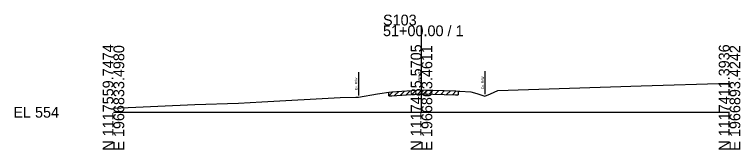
# Model space of a CAD drawing. Extents: x -26 to 163, y -10 to 24018.
# Drawn here: x -25.7 to 162.8, y 490.3 to 525.5 of the extents above; entities that cross this region are included whole.
import ezdxf

# ---------------------------------------------------------------- set-up
doc = ezdxf.new("R2010")
doc.units = 0
for name, color, linetype in [('RD_GPK_XS_Cell', 7, 'Continuous'), ('RD_XS_ExGround', 7, 'Continuous'), ('RD_XS_ExPaveRet', 7, 'Continuous'), ('RD_XS_ExRW', 7, 'Continuous'), ('RD_XS_TX_Elev_EX', 7, 'Continuous')]:
    doc.layers.add(name, color=color, linetype=linetype)

msp = doc.modelspace()

# ---------------------------------------------------------------- linework, layer by layer
at = {"layer": 'RD_GPK_XS_Cell'}
for p, q in [((80, 500), (80, 522.62)), ((0, 500), (80, 500)), ((80, 500), (160, 500))]:
    msp.add_line(p, q, dxfattribs=at)
at = {"layer": 'RD_XS_ExGround'}
msp.add_lwpolyline([(0, 501.08), (21.15, 501.99), (32.51, 502.36), (38.55, 502.7), (58.89, 503.85), (62.97, 503.9), (63.61, 503.91), (68.61, 504.78), (69.19, 504.87), (71.52, 505.26), (72.32, 505.31), (80.02, 505.81), (88.8, 505.56), (89.51, 505.54), (89.92, 505.51), (92.85, 505.32), (94.34, 504.91), (96.47, 504.2), (97.92, 504.77), (99.86, 505.71), (137.06, 506.89), (160, 507.54)], dxfattribs=at)
at = {"layer": 'RD_XS_ExPaveRet'}
for p, q in [((71.52, 504.26), (72.59, 505.33)), ((73.02, 504.36), (74.09, 505.43)), ((74.52, 504.45), (75.59, 505.52)), ((76.02, 504.55), (77.09, 505.62)), ((77.52, 504.65), (78.59, 505.72)), ((79.02, 504.75), (80.09, 505.81)), ((80.52, 504.8), (81.49, 505.77)), ((82.02, 504.75), (82.99, 505.73)), ((83.52, 504.71), (84.49, 505.68)), ((85.02, 504.67), (85.99, 505.64)), ((86.52, 504.62), (87.49, 505.6)), ((88.02, 504.58), (88.99, 505.55)), ((89.51, 505.54), (89.51, 504.54)), ((71.52, 504.26), (71.52, 505.26)), ((71.52, 504.26), (72.32, 504.31)), ((72.32, 504.31), (80.02, 504.81)), ((80.02, 504.81), (88.8, 504.56)), ((88.8, 504.56), (89.51, 504.54))]:
    msp.add_line(p, q, dxfattribs=at)
at = {"layer": 'RD_XS_ExRW'}
for p, q in [((63.61, 510.41), (63.61, 504.41)), ((96.47, 510.7), (96.47, 504.7))]:
    msp.add_line(p, q, dxfattribs=at)

# ---------------------------------------------------------------- texts
at = {"layer": 'RD_GPK_XS_Cell'}
for s, p in [('S103', (70, 522.62)), ('51+00.00 / 1', (70, 519.82)), ('EL 554', (-26, 498.6))]:
    msp.add_text(s, height=2.8, dxfattribs=at).set_placement(p)
for s, p in [('N 1117559.7474', (0, 490)), ('E 1966833.4980', (2.8, 490)), ('N 1117485.5705', (80, 490)), ('E 1966863.4611', (82.8, 490)), ('N 1117411.3936', (160, 490)), ('E 1966893.4242', (162.8, 490))]:
    msp.add_text(s, height=2.8, rotation=90, dxfattribs=at).set_placement(p)
at = {"layer": 'RD_XS_ExRW'}
for p in [(96.22, 506.04), (63.36, 505.75)]:
    msp.add_text('Ex. R/W ', height=0.65, rotation=90, dxfattribs=at).set_placement(p)
at = {"layer": 'RD_XS_TX_Elev_EX'}
msp.add_text('559.81', height=0.8, rotation=90, dxfattribs=at).set_placement((79.9, 507.81))

doc.saveas('drawing.dxf')
